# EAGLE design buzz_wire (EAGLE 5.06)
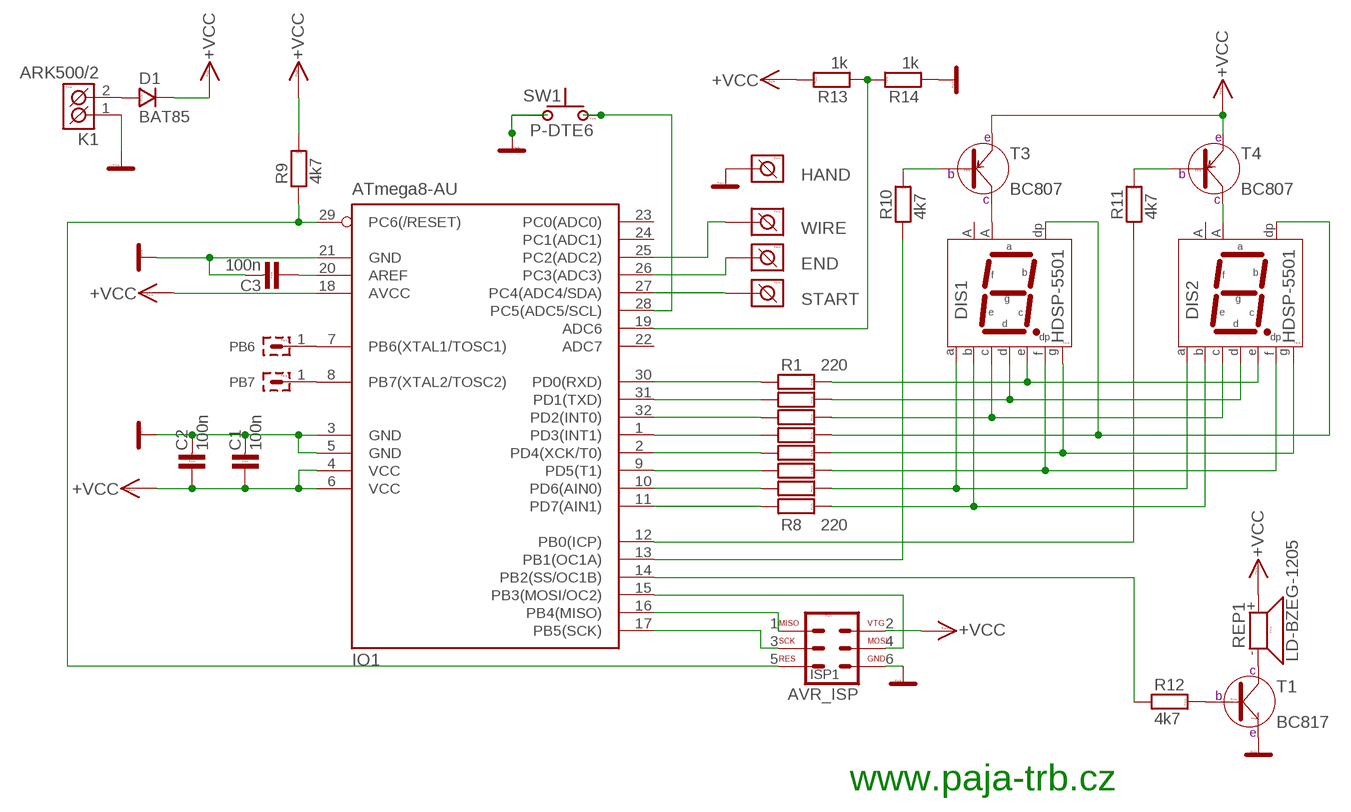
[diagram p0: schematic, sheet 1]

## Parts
C1  100n  C-KER_0805  [0805]
C2  100n  C-KER_0805  [0805]
C3  100n  C-KER_0805  [0805]
D1  BAT85  D_SOD-80  [SOD-80]
DIS1  HDSP-5501  [HDSP-M]
DIS2  HDSP-5501  [HDSP-M]
END  ARK500/1  [ARK500/1]
HAND  ARK500/1  [ARK500/1]
IO1  ATmega8-AU  MEGA8-AI  [TQFP32-08]
ISP1  AVR_ISP  [MLW06G]
K1  ARK500/2  [ARK500/2]
PB6  S1G1_JUMP  [S1G1_JUM]
PB7  S1G1_JUMP  [S1G1_JUM]
R1  220  R_1206  [1206]
R2  220  R_1206  [1206]
R3  220  R_1206  [1206]
R4  220  R_1206  [1206]
R5  220  R_1206  [1206]
R6  220  R_1206  [1206]
R7  220  R_1206  [1206]
R8  220  R_1206  [1206]
R9  4k7  R_1206  [1206]
R10  4k7  R_1206  [1206]
R11  4k7  R_1206  [1206]
R12  4k7  R_1206  [1206]
R13  1k  R_0805  [0805]
R14  1k  R_0805  [0805]
REP1  LD-BZEG-1205  SIR_1205  [LD-BZEG-1205]
START  ARK500/1  [ARK500/1]
SW1  P-DTE6  [P-DTE6]
T1  BC817  [SOT-23]
T3  BC807  [SOT-23]
T4  BC807  [SOT-23]
WIRE  ARK500/1  [ARK500/1]

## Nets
GND: C1.2 C2.2 C3.2 HAND.1(K1) IO1.3(GND) IO1.5(GND) IO1.21(GND) ISP1.6 K1.1(K1) R14.1 SW1.2 SW1.2A T1.2(E)
N$1: D1.A K1.2(K2)
N$2: IO1.2(PD4(XCK/T0)) R8.1
N$3: IO1.11(PD7(AIN1)) R5.1
N$4: C3.1 IO1.20(AREF)
N$5: IO1.9(PD5(T1)) R7.1
N$6: IO1.16(PB4(MISO)) ISP1.1
N$7: IO1.17(PB5(SCK)) ISP1.3
N$8: IO1.15(PB3(MOSI/OC2)) ISP1.4
N$9: IO1.10(PD6(AIN0)) R6.1
N$10: IO1.1(PD3(INT1)) R4.1
N$11: IO1.32(PD2(INT0)) R3.1
N$12: IO1.31(PD1(TXD)) R2.1
N$13: IO1.30(PD0(RXD)) R1.1
N$14: R10.2 T3.1(B)
N$15: R11.2 T4.1(B)
N$16: REP1.- T1.3(C)
N$17: R12.2 T1.1(B)
N$18: DIS1.8(CA2) T3.3(C)
N$19: DIS2.8(CA2) T4.3(C)
N$20: DIS1.1(E) DIS2.1(E) R1.2
N$21: DIS1.2(D) DIS2.2(D) R2.2
N$22: DIS1.4(C) DIS2.4(C) R3.2
N$23: DIS1.5(DP) DIS2.5(DP) R4.2
N$24: DIS1.6(B) DIS2.6(B) R5.2
N$25: DIS1.7(A) DIS2.7(A) R6.2
N$26: DIS1.9(F) DIS2.9(F) R7.2
N$27: DIS1.10(G) DIS2.10(G) R8.2
N$28: IO1.12(PB0(ICP)) R11.1
N$29: IO1.27(PC4(ADC4/SDA)) START.1(K1)
N$30: IO1.13(PB1(OC1A)) R10.1
N$31: IO1.14(PB2(SS/OC1B)) R12.1
N$32: IO1.28(PC5(ADC5/SCL)) SW1.1 SW1.1A
N$35: IO1.25(PC2(ADC2)) WIRE.1(K1)
N$36: END.1(K1) IO1.26(PC3(ADC3))
N$38: IO1.7(PB6(XTAL1/TOSC1)) PB6.1
N$39: IO1.8(PB7(XTAL2/TOSC2)) PB7.1
PC3: IO1.19(ADC6) R13.1 R14.2
RESET: IO1.29(PC6(/RESET)) ISP1.5 R9.1
VCC: C1.1 C2.1 D1.K IO1.4(VCC) IO1.6(VCC) IO1.18(AVCC) ISP1.2 R9.2 R13.2 REP1.+ T3.2(E) T4.2(E) ; supply symbol labelled +VCC
Unconnected: DIS1.3(CA1) DIS2.3(CA1) IO1.22(ADC7) IO1.23(PC0(ADC0)) IO1.24(PC1(ADC1))

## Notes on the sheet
- www.paja-trb.cz

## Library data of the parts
C1-C3 = #PaJa_32:C-KER: Kondenzator - keramicky
D1 = #PaJa_32:D: Dioda - univerzální
DIS1 DIS2 = #PaJa_displeje:HDSP-5501: LED displej - SA - 14,2 mm - cervena
END HAND START WIRE = #PaJa_konektory:ARK500/1: Svorkovnice - roztec 5mm
IO1 = atmel:MEGA8: MICROCONTROLLER 8 Kbytes FLASH, 1 kbytes SRAM, 512 bytes EEPROM, USART, 6-channel 10 bit ADC, 2-channel 8 bit ADC Pin compatible with Atmega48, ATMega88, ATMega168 Source: avr.lbr
ISP1 = #PaJa_32:AVR_ISP: AVR ISP konektor (dle standardu)
K1 = #PaJa_konektory:ARK500/2: Svorkovnice - roztec 5mm - dvojita
PB6 PB7 = #PaJa_konektory:S1G1_JUMP: Radove konektory - koliky - 1x
R1-R14 = #PaJa_32:R: Rezistor
REP1 = #PaJa_32:SIR: Piezo-sirenka - 70dB - 3V az 16V
SW1 = #PaJa_prepinace:P-DT: Tlacitkovy spinac
T1 = #PaJa_32:BC817: SMD tranzistor - NPN - ekv. BC337
T3 T4 = #PaJa_32:BC807: SMD tranzistor - PNP - ekv. BC327

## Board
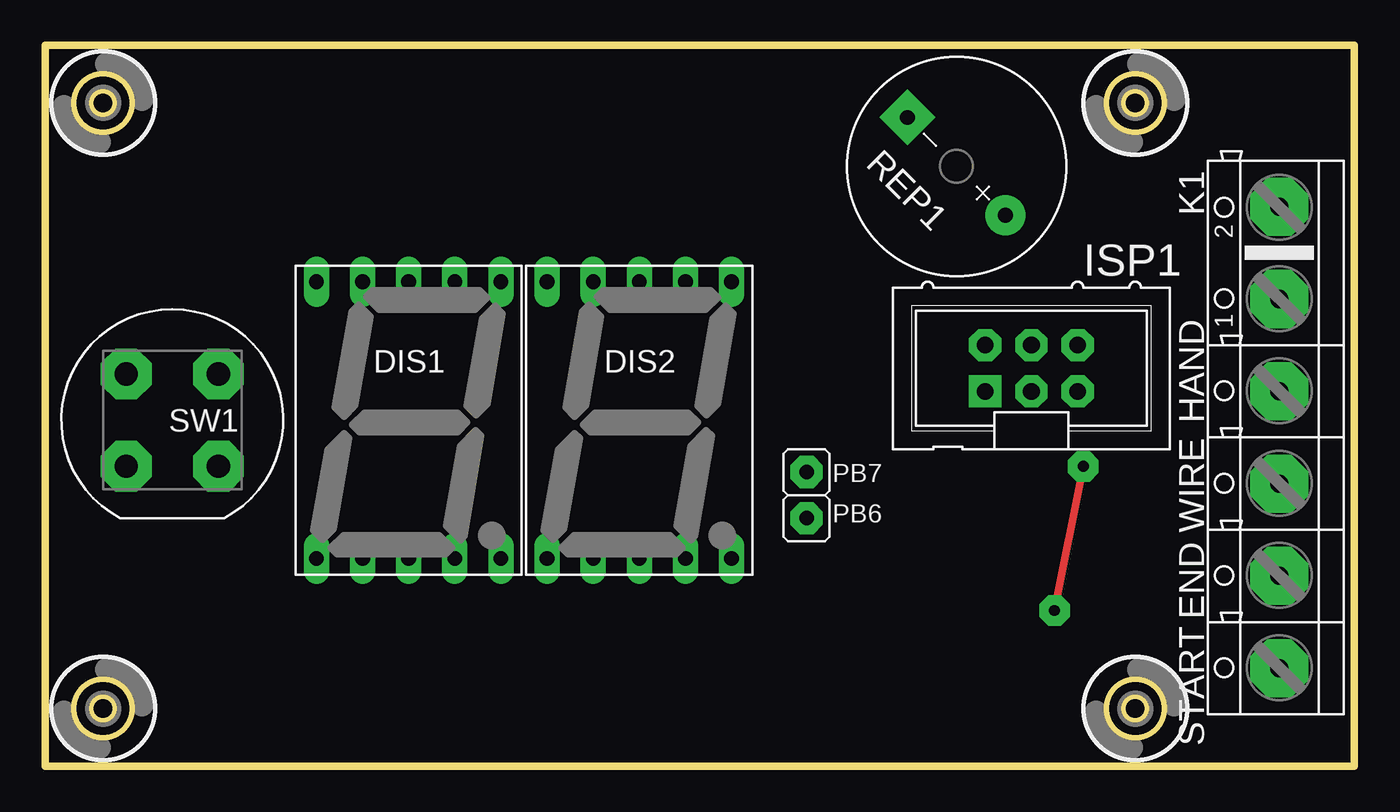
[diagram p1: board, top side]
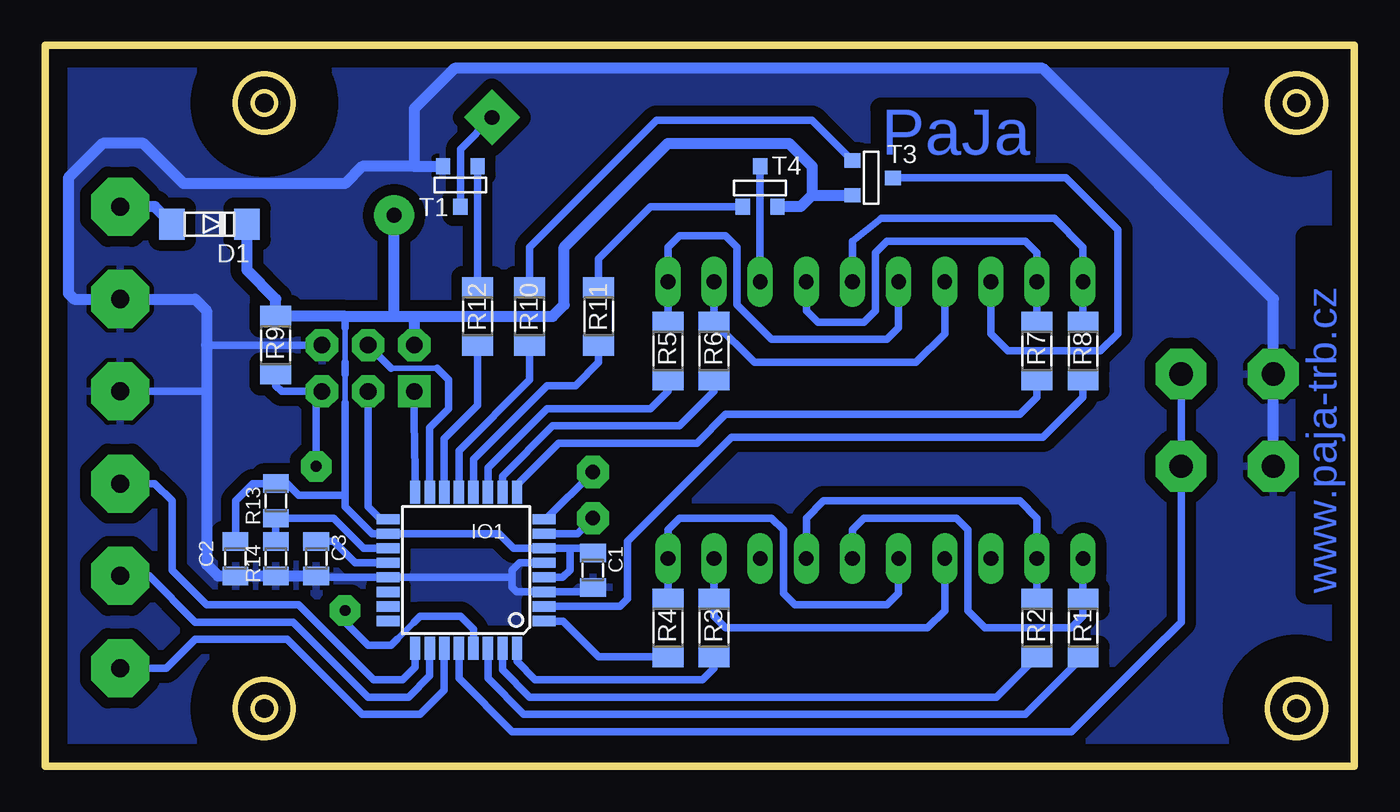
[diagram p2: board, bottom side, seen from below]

Size 72.06 x 39.68 mm. Coordinates in mm from the lower left corner, seen from the top.
Outline: 0,0 72.06,0 72.06,39.68 0,39.68 0,0
Copper layers (1*16): Top 0.035mm / dielectric 1.5mm / Bottom 0.035mm
Design rules "default": minimum track width 10mil, minimum drill 24mil, track to track 8mil, track to pad 8mil, pad to pad 8mil, via to via 8mil, smd to smd 8mil, copper to edge 40mil, drill to drill 8mil, minimum pad ring 10mil, minimum via ring 8mil, stop-mask expansion 4mil, vias tented up to drill 0mil, thermal gap 10mil

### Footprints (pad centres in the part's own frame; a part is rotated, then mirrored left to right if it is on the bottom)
0805 = smd 1.016 x 1.422: 1 -0.953,0; 2 0.953,0
SOD-80 = smd 1.397 x 1.702: A 1.905,0; K -2.223,0
HDSP-M = drill 0.813 pad 1.4 long: 1 -5.08,-7.62; 2 -2.54,-7.62; 3 0,-7.62; 4 2.54,-7.62; 5 5.08,-7.62; 6 5.08,7.62; 7 2.54,7.62; 8 0,7.62; 9 -2.54,7.62; 10 -5.08,7.62
ARK500/1 = drill 1 pad 3.2 octagon: 1 0,0
TQFP32-08 = smd 1.27 x 0.559: 1 -4.293,2.8; 2 -4.293,2; 3 -4.293,1.2; 4 -4.293,0.4; 5 -4.293,-0.4; 6 -4.293,-1.2; 7 -4.293,-2; 8 -4.293,-2.8; 17 4.293,-2.8; 18 4.293,-2; 19 4.293,-1.2; 20 4.293,-0.4; 21 4.293,0.4; 22 4.293,1.2; 23 4.293,2; 24 4.293,2.8 | smd 0.559 x 1.27: 9 -2.8,-4.293; 10 -2,-4.293; 11 -1.2,-4.293; 12 -0.4,-4.293; 13 0.4,-4.293; 14 1.2,-4.293; 15 2,-4.293; 16 2.8,-4.293; 25 2.8,4.293; 26 2,4.293; 27 1.2,4.293; 28 0.4,4.293; 29 -0.4,4.293; 30 -1.2,4.293; 31 -2,4.293; 32 -2.8,4.293
MLW06G = drill 0.914 pad 1.778 square: 1 -2.54,-1.27 | drill 0.914 pad 1.778 octagon: 2 -2.54,1.27; 3 0,-1.27; 4 0,1.27; 5 2.54,-1.27; 6 2.54,1.27
ARK500/2 = drill 1 pad 3.2 octagon: 1 -2.54,0; 2 2.54,0
S1G1_JUM = drill 0.8 pad 1.778 octagon: 1 0,0
1206 = smd 1.143 x 1.702: 1 -1.587,0; 2 1.587,0
LD-BZEG-1205 = drill 0.813 pad 2.184 round: + -3.81,0 | drill 0.813 pad 2.184 square: - 3.81,0
P-DTE6 = drill 1.27 pad 2.8 octagon: 1 -2.54,-2.54; 1A -2.54,2.54; 2 2.54,-2.54; 2A 2.54,2.54
SOT-23 = smd 0.787 x 0.889: 1 -0.953,-0.953; 2 0.953,-0.953; 3 0,1.27
HOLE_3,0 = hole 3.2: 0,0

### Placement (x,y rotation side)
C1  41.91,10.79 270 bottom
C2  61.59,11.43 270 bottom
C3  57.15,11.43 270 bottom
D1  63.18,29.84 180 bottom
DIS1  20,19.05 0 top
DIS2  32.7,19.05 0 top
END  67.94,10.48 90 top
HAND  67.94,20.64 90 top
IO1  48.9,10.79 180 bottom
ISP1  54.29,21.91 0 top
K1  67.94,28.26 90 top
PB6  41.91,13.65 0 top
PB7  41.91,16.19 0 top
R1  14.92,7.62 90 bottom
R2  17.46,7.62 90 bottom
R3  35.24,7.62 90 bottom
R4  37.78,7.62 90 bottom
R5  37.78,22.86 90 bottom
R6  35.24,22.86 90 bottom
R7  17.46,22.86 90 bottom
R8  14.92,22.86 90 bottom
R9  59.37,23.18 90 bottom
R10  45.4,24.77 90 bottom
R11  41.59,24.77 90 bottom
R12  48.26,24.77 90 bottom
R13  59.37,14.61 90 bottom
R14  59.37,11.43 90 bottom
REP1  50.16,33.02 135 top
START  67.94,5.4 90 top
SW1  6.99,19.05 180 top
T1  49.21,32.07 180 bottom
T3  26.67,32.38 270 bottom
T4  32.7,31.75 0 bottom
U$1  [HOLE_3,0]  3.17,3.17 0 top
U$2  [HOLE_3,0]  60.01,3.17 0 top
U$3  [HOLE_3,0]  60.01,36.51 0 top
U$4  [HOLE_3,0]  3.17,36.51 0 top
WIRE  67.94,15.56 90 top

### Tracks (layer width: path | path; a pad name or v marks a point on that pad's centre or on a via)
GND
  Bottom 0.406: IO1.5 45.95,11.2 46.35,10.79 46.35,10.48 | 46.35,10.48 46.35,9.84 46.11,9.6 IO1.3 42.16,9.6 C1.2 | 46.35,10.48 46.44,10.39 IO1.21 56.75,10.39 C3.2 | 63.18,23.18 ISP1.6 | 63.18,20.64 HAND.1
  Bottom 0.61: C3.2 R14.1 C2.2 62.55,10.48 63.18,11.11 63.18,20.64 63.18,23.18 63.18,25.08 63.82,25.72 K1.1 70.48,25.72 70.8,26.04 70.8,32.38 68.9,34.29 66.67,34.29 64.45,32.07 55.56,32.07 54.61,33.02 51.75,33.02 | 51.75,33.02 T1.2 | 51.75,33.02 51.75,36.2 49.53,38.42 17.14,38.42 4.45,25.72 SW1.2 SW1.2A
  pour Bottom (isolate 0.61): 0,0 0,39.69 72.07,39.69 72.07,0
N$1
  Bottom 0.61: D1.A 66.04,30.8 K1.2
N$2
  Bottom 0.406: IO1.2 40.42,8.79 40.01,9.21 40.01,12.38 34.29,18.1 17.14,18.1 14.92,20.32 R8.1
N$3
  Bottom 0.406: IO1.11 47.7,16.44 44.45,19.68 38.73,19.68 37.78,20.64 R5.1
N$4
  Bottom 0.406: IO1.20 55.01,11.2 56.2,12.38 C3.1
N$5
  Bottom 0.406: IO1.9 46.09,15.5 43.81,17.78 36.2,17.78 34.61,19.37 18.41,19.37 17.46,20.32 R7.1
N$6
  Bottom 0.406: IO1.16 51.7,16.25 51.75,19.05 ISP1.1
N$7
  Bottom 0.406: IO1.17 53.6,13.6 54.29,14.29 ISP1.3
N$8
  Bottom 0.305: 50.48,21.91 53.02,21.91
  Bottom 0.406: 53.02,21.91 ISP1.4 | IO1.15 50.9,18.64 49.85,19.68 49.85,21.27 50.48,21.91
N$9
  Bottom 0.406: R6.1 35.24,20.64 37.15,18.73 44.13,18.73 46.9,15.97 IO1.10
N$10
  Bottom 0.406: R4.1 41.59,6.03 43.55,8 IO1.1
N$11
  Bottom 0.406: R3.1 35.24,5.4 35.88,4.76 36.2,4.76 45.09,4.76 46.09,5.77 IO1.32
N$12
  Bottom 0.406: R2.1 19.68,3.81 45.4,3.81 46.9,5.3 IO1.31
N$13
  Bottom 0.406: R1.1 18.1,2.86 41.59,2.86 | 41.59,2.86 41.91,2.86 | IO1.30 47.7,4.83 45.72,2.86 41.59,2.86
N$14
  Bottom 0.406: R10.2 45.4,28.57 38.42,35.56 29.84,35.56 T3.1
N$15
  Bottom 0.406: T4.1 38.73,30.8 41.59,27.94 R11.2
N$16
  Bottom 0.406: T1.3 49.21,33.97 REP1.-
N$17
  Bottom 0.406: R12.2 T1.1
N$18
  Bottom 0.406: DIS1.8 20,23.81 19.05,22.86 13.97,22.86 13.02,23.81 13.02,29.53 15.88,32.38 T3.3
N$19
  Bottom 0.406: DIS2.8 T4.3
N$20
  Bottom 0.406: DIS2.1 27.62,13.02 26.99,13.65 21.91,13.65 21.27,13.02 21.27,8.57 20.32,7.62 15.56,7.62 14.92,8.26 R1.2 DIS1.1
N$21
  Bottom 0.406: DIS2.2 30.16,13.65 29.21,14.61 18.41,14.61 17.46,13.65 DIS1.2 R2.2
N$22
  Bottom 0.406: R3.2 35.24,8.26 34.61,7.62 23.5,7.62 22.54,8.57 DIS1.4 | R3.2 DIS2.4 R3.2
N$23
  Bottom 0.406: R4.2 DIS2.5 37.78,13.02 37.15,13.65 32.07,13.65 31.43,13.02 31.43,9.53 30.8,8.89 25.72,8.89 25.08,9.53 DIS1.5
N$24
  Bottom 0.406: R5.2 DIS2.6 37.78,28.57 37.15,29.21 34.61,29.21 33.97,28.57 33.97,25.4 32.07,23.5 25.72,23.5 25.08,24.13 DIS1.6
N$25
  Bottom 0.406: DIS2.7 R6.2 33.02,22.23 24.13,22.23 22.54,23.81 DIS1.7
N$26
  Bottom 0.406: DIS2.9 30.16,25.08 29.53,24.45 26.99,24.45 26.35,25.08 26.35,28.26 25.72,28.89 18.1,28.89 17.46,28.26 DIS1.9 R7.2
N$27
  Bottom 0.406: R8.2 DIS1.10 14.92,28.57 16.51,30.16 26.04,30.16 27.62,28.89 DIS2.10
N$28
  Bottom 0.406: IO1.12 48.49,16.91 44.45,20.95 42.86,20.95 41.59,22.23 R11.1
N$29
  Bottom 0.406: IO1.27 50.09,4.2 51.44,2.86 54.61,2.86 58.74,6.99 63.82,6.99 65.41,5.4 START.1
N$30
  Bottom 0.406: IO1.13 49.3,17.38 45.4,21.27 R10.1
N$31
  Bottom 0.406: IO1.14 50.09,18.03 48.26,19.86 R12.1
N$32
  Bottom 0.406: IO1.28 49.3,4.84 46.35,1.91 15.56,1.91 11.27,6.19 9.53,7.94 SW1.1A SW1.1
N$35
  Bottom 0.406: 51.7,5.77 IO1.25 51.7,5.46 52.39,4.76 53.98,4.76 58.1,8.89 63.18,8.89 65.09,10.79 65.09,14.61 66.04,15.56 WIRE.1
N$36
  Bottom 0.406: IO1.26 50.9,4.99 52.07,3.81 54.29,3.81 58.42,7.94 63.82,7.94 66.36,10.48 END.1
N$38
  Bottom 0.406: IO1.7 42.77,12.79 PB6.1
N$39
  Bottom 0.406: IO1.8 44.51,13.6 PB7.1
PC3
  Bottom 0.406: IO1.19 54.54,11.99 56.2,13.65 R13.1 R14.2
RESET  (via drill 0.6 pad 1.68)
  Top 0.406: v55.56,8.57 v57.15,16.51
  Bottom 0.305: 51.75,7.94 52.7,6.99
  Bottom 0.406: IO1.29 48.49,7.54 49.21,8.26 51.44,8.26 51.75,7.94 | 52.7,6.99 53.02,6.67 54.29,6.67 55.56,7.94 v55.56,8.57 | R9.1 59.37,20.95 59.05,20.64 ISP1.5 57.15,20.32 v57.15,16.51
VCC
  Bottom 0.305: 55.56,22.23 55.56,24.13 | 55.56,20 55.56,21.59
  Bottom 0.406: IO1.4 43.58,10.39 43.18,10.79 43.18,11.99 | 43.18,11.99 42.16,11.99 C1.1 | 43.18,11.99 IO1.6 46.28,11.99 47.09,12.79 IO1.18 54.07,12.79 55.56,14.29 55.56,14.92 | 55.56,24.13 55.56,24.77 | 55.56,14.92 55.56,20 | 55.56,14.92 58.1,14.92 58.74,15.56 R13.2 60.64,15.56 61.59,14.61 C2.1 | 51.75,24.77 52.86,24.77 | 55.56,21.59 55.56,22.23
  Bottom 0.61: 29.84,31.43 30.48,30.8 T4.2 | 51.75,24.77 55.56,24.77 R9.2 59.37,25.72 60.96,27.3 D1.K | 51.75,24.77 ISP1.2 | 29.84,31.43 29.84,33.02 31.11,34.29 37.78,34.29 43.5,28.57 43.5,25.4 44.13,24.77 51.75,24.77 | 29.84,31.43 T3.2 | 52.86,24.77 REP1.+

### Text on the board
Bottom: PaJa | www.paja-trb.cz
PaJa: www.paja-trb.cz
